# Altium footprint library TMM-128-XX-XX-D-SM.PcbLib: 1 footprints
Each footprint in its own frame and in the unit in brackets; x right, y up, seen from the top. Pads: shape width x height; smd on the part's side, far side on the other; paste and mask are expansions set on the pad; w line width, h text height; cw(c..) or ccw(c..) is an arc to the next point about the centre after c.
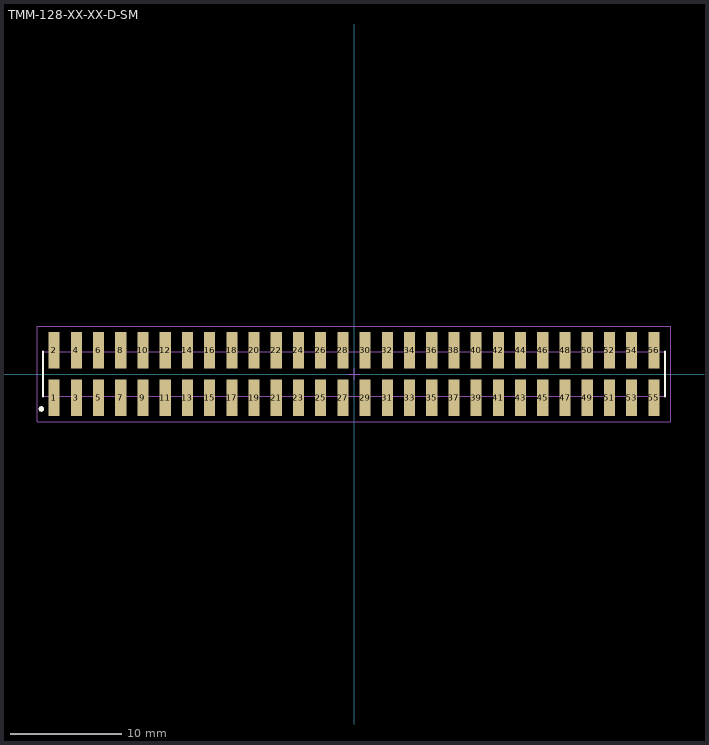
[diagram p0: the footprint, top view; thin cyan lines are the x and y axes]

## TMM-128-XX-XX-D-SM [mm] "2.00mm pitch, 56 pin, terminal strip; double row, SMT"
height 2.77
pads (56):
  rect 1x3.3 smd mask+0: 1(-27,-2.15) 2(-27,2.15) 3(-25,-2.15) 4(-25,2.15) 5(-23,-2.15) 6(-23,2.15) 7(-21,-2.15) 8(-21,2.15) 9(-19,-2.15) 10(-19,2.15) 11(-17,-2.15) 12(-17,2.15) 13(-15,-2.15) 14(-15,2.15) 15(-13,-2.15) 16(-13,2.15) 17(-11,-2.15) 18(-11,2.15) 19(-9,-2.15) 20(-9,2.15) 21(-7,-2.15) 22(-7,2.15) 23(-5,-2.15) 24(-5,2.15) 25(-3,-2.15) 26(-3,2.15) 27(-1,-2.15) 28(-1,2.15) 29(1,-2.15) 30(1,2.15) 31(3,-2.15) 32(3,2.15) 33(5,-2.15) 34(5,2.15) 35(7,-2.15) 36(7,2.15) 37(9,-2.15) 38(9,2.15) 39(11,-2.15) 40(11,2.15) 41(13,-2.15) 42(13,2.15) 43(15,-2.15) 44(15,2.15) 45(17,-2.15) 46(17,2.15) 47(19,-2.15) 48(19,2.15) 49(21,-2.15) 50(21,2.15) 51(23,-2.15) 52(23,2.15) 53(25,-2.15) 54(25,2.15) 55(27,-2.15) 56(27,2.15)
Top Overlay:
  circle w0.25: c-28.15,-3.15 r0.125
  lines w0.2: -28,-2 -28,2 ; 28,-2 28,2
Mechanical 12:
  lines w0.001: -28,-2 28,-2 28,2 -28,2 -28,-2
Mechanical 13:
  lines w0.1: -28,-2 28,-2 28,2 -28,2 -28,-2
  text ".Designator" at 0,-0.127 h1.52
Mechanical 15:
  lines w0.05: -0.5,0 0.5,0 ; 0,-0.5 0,0.5 ; -28.5,-4.3 28.5,-4.3 28.5,4.3 -28.5,4.3 -28.5,-4.3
